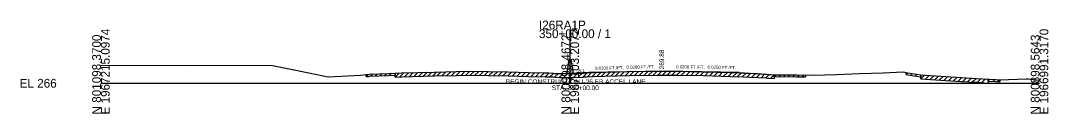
# Model space of a CAD drawing. Extents: x -26 to 304, y -10 to 7527.
# Drawn here: x -25.7 to 302.8, y -9.7 to 20.1 of the extents above; entities that cross this region are included whole.
import ezdxf

# ---------------------------------------------------------------- set-up
doc = ezdxf.new("R2010")
doc.units = 0
for name, color, linetype in [('RD_GPK_XS_Cell', 7, 'Continuous'), ('RD_XS_Base', 7, 'Continuous'), ('RD_XS_EarthShd', 7, 'Continuous'), ('RD_XS_EwShp', 7, 'Continuous'), ('RD_XS_ExGround', 7, 'Continuous'), ('RD_XS_ExPaveRet', 7, 'Continuous'), ('RD_XS_Misc_Line', 7, 'Continuous'), ('RD_XS_Pave', 7, 'Continuous'), ('RD_XS_PaveShd', 7, 'Continuous'), ('RD_XS_TX_Elev_EX', 7, 'Continuous'), ('RD_XS_TX_Elev_PR', 7, 'Continuous'), ('RD_XS_TX_MkPT', 7, 'Continuous'), ('RD_XS_TX_Profile', 7, 'Continuous'), ('RD_XS_TX_Station', 7, 'Continuous')]:
    doc.layers.add(name, color=color, linetype=linetype)

msp = doc.modelspace()

# ---------------------------------------------------------------- linework, layer by layer
at = {"layer": 'RD_GPK_XS_Cell'}
for p, q in [((150, 0), (150, 17.28)), ((0, 0), (150, 0)), ((150, 0), (300, 0))]:
    msp.add_line(p, q, dxfattribs=at)
at = {"layer": 'RD_XS_Base'}
msp.add_line((150, 3.11), (150, 3.16), dxfattribs=at)
at = {"layer": 'RD_XS_EarthShd'}
for p, q in [((149, 3.18), (149.67, 7.66)), ((150, 7.66), (149.67, 7.66)), ((150, 7.66), (150.33, 7.66)), ((151, 3.18), (150.33, 7.66))]:
    msp.add_line(p, q, dxfattribs=at)
at = {"layer": 'RD_XS_ExGround'}
msp.add_lwpolyline([(0, 5.66), (28.67, 5.76), (54.78, 5.73), (61.72, 4.28), (72.58, 2.02), (82.96, 2.63), (84.77, 2.76), (85.33, 2.79), (85.63, 2.81), (85.88, 2.93), (91.94, 3.16), (94.01, 3.24), (96.13, 3.3), (106.47, 3.59), (113.66, 3.73), (118.38, 3.83), (123.9, 3.73), (130.15, 3.63), (136.69, 3.47), (141.95, 3.36), (143.14, 3.33), (144.68, 3.28), (145.07, 3.17), (146.52, 3.14), (148.52, 3.1), (149.5, 3.1), (150, 3.11), (151.21, 3.13), (154.28, 3.2), (154.52, 3.3), (155.15, 3.32), (157.36, 3.42), (160.93, 3.51), (168.92, 3.72), (177.8, 3.84), (180.87, 3.89), (184.46, 3.83), (192.64, 3.69), (201.11, 3.44), (205.29, 3.32), (207.27, 3.23), (212.57, 2.96), (213.16, 2.86), (213.62, 2.84), (215.2, 2.75), (222.37, 2.7), (227.61, 2.58), (235.05, 2.79), (242.41, 3.1), (250.01, 3.36), (256.38, 3.62), (257.91, 3.37), (262.01, 2.69), (263.5, 2.58), (274.94, 1.86), (279.82, 1.55), (285.96, 1.18), (287.28, 1.13), (295.68, 1.41), (296.32, 1.43), (296.98, 1.36), (300, 1.04)], dxfattribs=at)
at = {"layer": 'RD_XS_ExPaveRet'}
for p, q in [((257.4, 2.83), (257.4, 3.46)), ((84.77, 2.13), (84.77, 2.76)), ((84.77, 2.13), (85.33, 2.17)), ((85.33, 2.17), (85.63, 2.19)), ((85.63, 2.19), (85.88, 2.3)), ((85.88, 2.3), (91.94, 2.53)), ((91.94, 2.53), (94, 2.61)), ((94, 1.99), (94, 3.24)), ((94, 3.24), (94, 2.61)), ((94, 1.99), (94.01, 1.99)), ((94.01, 1.99), (96.13, 2.05)), ((96.13, 2.05), (106.47, 2.34)), ((106.47, 2.34), (113.66, 2.48)), ((113.66, 2.48), (118.38, 2.58)), ((118.38, 2.58), (123.9, 2.48)), ((123.9, 2.48), (130.15, 2.38)), ((130.15, 2.38), (136.69, 2.22)), ((136.69, 2.22), (141.95, 2.11)), ((141.95, 2.11), (143.14, 2.08)), ((143.14, 2.08), (144.68, 2.03)), ((144.68, 2.03), (145.07, 1.92)), ((145.07, 1.92), (146.52, 1.89)), ((146.52, 1.89), (148.52, 1.85)), ((148.52, 1.85), (149.5, 1.85)), ((149.5, 1.85), (150, 1.86)), ((150, 1.86), (151.21, 1.88)), ((151.21, 1.88), (154.28, 1.95)), ((154.28, 1.95), (154.52, 2.05)), ((154.52, 2.05), (155.15, 2.07)), ((155.15, 2.07), (157.36, 2.17)), ((157.36, 2.17), (160.93, 2.26)), ((160.93, 2.26), (168.92, 2.47)), ((168.92, 2.47), (177.8, 2.59)), ((177.8, 2.59), (180.87, 2.64)), ((180.87, 2.64), (184.46, 2.58)), ((184.46, 2.58), (192.64, 2.44)), ((192.64, 2.44), (201.11, 2.19)), ((201.11, 2.19), (205.29, 2.07)), ((205.29, 2.07), (207.27, 1.98)), ((207.27, 1.98), (212.57, 1.71)), ((212.57, 1.71), (213.16, 1.61)), ((213.16, 1.61), (213.62, 1.59)), ((213.62, 1.59), (215.2, 1.5)), ((215.2, 2.75), (215.2, 1.5)), ((215.2, 2.12), (215.2, 2.75)), ((215.2, 2.12), (222.37, 2.08)), ((222.37, 2.08), (225.2, 2.01)), ((225.2, 2.64), (225.2, 2.01)), ((257.4, 2.83), (257.91, 2.75)), ((257.91, 2.75), (262.01, 2.06)), ((262.01, 1.44), (262.01, 2.69)), ((262.01, 2.69), (262.01, 2.06)), ((262.01, 1.44), (263.5, 1.33)), ((263.5, 1.33), (274.94, 0.61)), ((274.94, 0.61), (279.82, 0.3)), ((279.82, 0.3), (283.57, 0.07)), ((283.57, 1.32), (283.57, 0.07)), ((283.57, 0.7), (283.57, 1.32)), ((283.57, 0.7), (285.96, 0.56)), ((285.96, 0.56), (287.28, 0.5)), ((287.28, 1.13), (287.28, 0.5))]:
    msp.add_line(p, q, dxfattribs=at)
at = {"layer": 'RD_XS_Misc_Line'}
for p, q in [((95.5, 2.03), (96.79, 3.32)), ((97, 2.07), (98.29, 3.36)), ((98.5, 2.11), (99.79, 3.4)), ((100, 2.16), (101.29, 3.44)), ((101.5, 2.2), (102.79, 3.48)), ((103, 2.24), (104.29, 3.53)), ((104.5, 2.28), (105.79, 3.57)), ((106, 2.32), (107.28, 3.6)), ((107.5, 2.36), (108.78, 3.63)), ((109, 2.39), (110.28, 3.66)), ((110.5, 2.42), (111.78, 3.69)), ((112, 2.45), (113.28, 3.72)), ((113.5, 2.48), (114.78, 3.75)), ((115, 2.51), (116.28, 3.78)), ((116.5, 2.54), (117.78, 3.82)), ((118, 2.57), (119.24, 3.81)), ((119.5, 2.56), (120.73, 3.79)), ((121, 2.53), (122.23, 3.76)), ((122.5, 2.51), (123.73, 3.74)), ((124, 2.48), (125.23, 3.71)), ((125.5, 2.46), (126.73, 3.69)), ((127, 2.43), (128.23, 3.66)), ((128.5, 2.41), (129.73, 3.64)), ((130, 2.38), (131.22, 3.6)), ((131.5, 2.35), (132.72, 3.57)), ((133, 2.31), (134.22, 3.53)), ((134.5, 2.28), (135.72, 3.5)), ((136, 2.24), (137.22, 3.46)), ((137.5, 2.21), (138.72, 3.43)), ((139, 2.17), (140.22, 3.4)), ((140.5, 2.14), (141.72, 3.36)), ((142, 2.11), (143.22, 3.33)), ((154, 1.94), (155.39, 3.33)), ((155.5, 2.09), (156.81, 3.4)), ((157, 2.15), (158.29, 3.44)), ((158.5, 2.2), (159.78, 3.48)), ((160, 2.24), (161.28, 3.52)), ((161.5, 2.27), (162.78, 3.56)), ((163, 2.31), (164.28, 3.6)), ((164.5, 2.35), (165.78, 3.63)), ((166, 2.39), (167.28, 3.67)), ((167.5, 2.43), (168.78, 3.71)), ((169, 2.47), (170.27, 3.73)), ((170.5, 2.49), (171.77, 3.76)), ((172, 2.51), (173.27, 3.78)), ((173.5, 2.53), (174.77, 3.8)), ((175, 2.55), (176.27, 3.82)), ((176.5, 2.58), (177.77, 3.84)), ((178, 2.6), (179.27, 3.87)), ((179.5, 2.62), (180.77, 3.89)), ((181, 2.64), (182.23, 3.86)), ((182.5, 2.61), (183.73, 3.84)), ((184, 2.58), (185.23, 3.81)), ((185.5, 2.56), (186.73, 3.79)), ((187, 2.53), (188.23, 3.76)), ((188.5, 2.51), (189.73, 3.74)), ((190, 2.48), (191.23, 3.71)), ((191.5, 2.46), (192.73, 3.68)), ((193, 2.43), (194.21, 3.64)), ((194.5, 2.38), (195.71, 3.6)), ((196, 2.34), (197.21, 3.55)), ((197.5, 2.29), (198.71, 3.51)), ((199, 2.25), (200.21, 3.47)), ((200.5, 2.21), (201.71, 3.42)), ((202, 2.16), (203.22, 3.38)), ((203.5, 2.12), (204.72, 3.34)), ((257.4, 2.83), (257.93, 3.37)), ((84.77, 2.13), (85.43, 2.8)), ((86.27, 2.32), (86.92, 2.97)), ((87.77, 2.37), (88.42, 3.02)), ((89.27, 2.43), (89.92, 3.08)), ((90.77, 2.49), (91.42, 3.14)), ((92.27, 2.55), (92.92, 3.2)), ((94, 1.99), (95.29, 3.27)), ((143.5, 2.07), (144.71, 3.28)), ((145, 1.94), (146.2, 3.15)), ((146.5, 1.89), (147.73, 3.12)), ((148, 1.86), (149.24, 3.1)), ((149.5, 1.85), (150.77, 3.12)), ((151, 1.88), (152.28, 3.16)), ((152.5, 1.91), (153.78, 3.19)), ((205, 2.08), (206.2, 3.28)), ((206.5, 2.01), (207.69, 3.2)), ((208, 1.94), (209.19, 3.13)), ((209.5, 1.86), (210.69, 3.05)), ((211, 1.79), (212.19, 2.98)), ((212.5, 1.71), (213.63, 2.84)), ((214, 1.57), (215.18, 2.75)), ((215.2, 2.12), (215.82, 2.74)), ((216.7, 2.11), (217.32, 2.73)), ((218.2, 2.1), (218.82, 2.72)), ((219.7, 2.09), (220.32, 2.72)), ((221.2, 2.08), (221.82, 2.71)), ((222.7, 2.07), (223.31, 2.68)), ((224.2, 2.03), (224.81, 2.65)), ((258.9, 2.58), (259.43, 3.12)), ((260.4, 2.33), (260.93, 2.87)), ((262.01, 1.44), (263.18, 2.61)), ((263.51, 1.33), (264.69, 2.51)), ((265.01, 1.24), (266.19, 2.41)), ((266.51, 1.14), (267.69, 2.32)), ((268.01, 1.05), (269.19, 2.22)), ((269.51, 0.95), (270.69, 2.13)), ((271.01, 0.86), (272.19, 2.03)), ((272.51, 0.76), (273.69, 1.94)), ((274.01, 0.67), (275.19, 1.84)), ((275.51, 0.57), (276.69, 1.75)), ((277.01, 0.48), (278.19, 1.65)), ((278.51, 0.38), (279.69, 1.56)), ((280.01, 0.29), (281.19, 1.47)), ((281.51, 0.2), (282.69, 1.38)), ((283.57, 0.7), (284.16, 1.29)), ((285.07, 0.61), (285.66, 1.2)), ((286.57, 0.53), (287.17, 1.13))]:
    msp.add_line(p, q, dxfattribs=at)
at = {"layer": 'RD_XS_Pave'}
for p, q in [((180, 3.88), (156, 3.4)), ((204, 3.4), (180, 3.88))]:
    msp.add_line(p, q, dxfattribs=at)
at = {"layer": 'RD_XS_PaveShd'}
for p, q in [((156, 3.4), (150, 3.16)), ((204, 3.4), (214, 2.82))]:
    msp.add_line(p, q, dxfattribs=at)
at = {"layer": 'RD_XS_TX_Elev_PR'}
for p, q in [((154.28, 3.2), (154.52, 3.3)), ((154.52, 3.3), (155.15, 3.32)), ((155.15, 3.32), (157.36, 3.42)), ((157.36, 3.42), (160.93, 3.51)), ((160.93, 3.51), (168.92, 3.72)), ((168.92, 3.72), (177.8, 3.84)), ((177.8, 3.84), (180.87, 3.89)), ((180.87, 3.89), (184.46, 3.83)), ((184.46, 3.83), (192.64, 3.69)), ((192.64, 3.69), (201.11, 3.44)), ((201.11, 3.44), (204, 3.36)), ((204, 3.36), (205.29, 3.32)), ((205.29, 3.32), (206.28, 3.27)), ((150, 3.11), (151.21, 3.13)), ((151.21, 3.13), (154.28, 3.2)), ((206.28, 3.27), (207.27, 3.23)), ((207.27, 3.23), (209.92, 3.09)), ((209.92, 3.09), (212.57, 2.96)), ((212.57, 2.96), (213.16, 2.86)), ((213.16, 2.86), (213.62, 2.84)), ((213.62, 2.84), (214, 2.82))]:
    msp.add_line(p, q, dxfattribs=at)

# ---------------------------------------------------------------- texts
at = {"layer": 'RD_GPK_XS_Cell'}
for s, p in [('I26RA1P', (140, 17.28)), ('350+00.00 / 1', (140, 14.48)), ('EL 266', (-26, -1.4))]:
    msp.add_text(s, height=2.8, dxfattribs=at).set_placement(p)
for s, p in [('E 1967215.0974', (2.8, -10)), ('E 1967103.2072', (152.8, -10)), ('E 1966991.3170', (302.8, -10)), ('N 801098.3700', (0, -10)), ('N 800998.4672', (150, -10)), ('N 800898.5643', (300, -10))]:
    msp.add_text(s, height=2.8, rotation=90, dxfattribs=at).set_placement(p)
at = {"layer": 'RD_XS_EwShp'}
for s, p in [('BEGIN CONSTRUCTION I-26 EB ACCEL LANE', (129.39, -0.23)), ('STA. 350+00.00', (144.1, -2.2))]:
    msp.add_text(s, height=1.5, dxfattribs=at).set_placement(p)
at = {"layer": 'RD_XS_TX_Elev_EX'}
msp.add_text('269.11', height=1, rotation=90, dxfattribs=at).set_placement((151, 3.11))
at = {"layer": 'RD_XS_TX_MkPT'}
msp.add_text('25:1', height=1, rotation=2.2906, dxfattribs=at).set_placement((151.94, 3.48))
at = {"layer": 'RD_XS_TX_Profile'}
for rotation, p in [(1.1458, (157.92, 4.32)), (1.1458, (167.98, 4.64)), (358.8542, (183.83, 4.8)), (358.8542, (193.89, 4.68))]:
    msp.add_text('0.0200 FT./FT.', height=1, rotation=rotation, dxfattribs=at).set_placement(p)
at = {"layer": 'RD_XS_TX_Station'}
msp.add_text(' 269.88', height=1.5, rotation=90, dxfattribs=at).set_placement((180, 3.88))

doc.saveas('drawing.dxf')
